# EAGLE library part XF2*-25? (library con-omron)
OMRON FPC Connector Source : http://www.omron.com/ecb/products/pdf/fpc.pdf
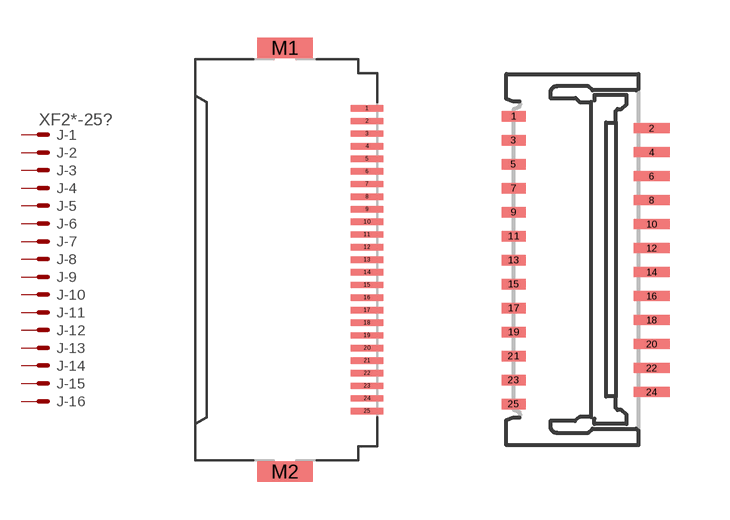
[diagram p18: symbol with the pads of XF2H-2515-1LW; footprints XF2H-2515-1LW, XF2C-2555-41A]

Designator prefix J; gates -1=PV -2=P -3=P -4=P -5=P -6=P -7=P -8=P -9=P -10=P -11=P -12=P -13=P -14=P -15=P -16=P -17=P -18=P -19=P -20=P -21=P -22=P -23=P -24=P -25=P

## XF2H-2515-1LW (OC_FARNELL: unknown; OC_NEWARK: unknown)  [XF2H-2515-1LW]
1  -1:MSV  pas
2  -2:MS  pas
3  -3:MS  pas
4  -4:MS  pas
5  -5:MS  pas
6  -6:MS  pas
7  -7:MS  pas
8  -8:MS  pas
9  -9:MS  pas
10  -10:MS  pas
11  -11:MS  pas
12  -12:MS  pas
13  -13:MS  pas
14  -14:MS  pas
15  -15:MS  pas
16  -16:MS  pas
17  -17:MS  pas
18  -18:MS  pas
19  -19:MS  pas
20  -20:MS  pas
21  -21:MS  pas
22  -22:MS  pas
23  -23:MS  pas
24  -24:MS  pas
25  -25:MS  pas

## XF2C-2555-41A (MPN: XF2C-2555-41A; OC_FARNELL: unknown; OC_NEWARK: 78M3584)  [XF2C-2555-41A]
Pads as for XF2H-2515-1LW

## Footprint XF2H-2515-1LW (pad centres in mm)
Standard Rotary Backlock Type (0.5 mm-pitch) Source : http://www.omron.com/ecb/products/pdf/fpc.pdf
smd 1.3 x 0.25: 1 3.175,6; 2 3.175,5.5; 3 3.175,5; 4 3.175,4.5; 5 3.175,4; 6 3.175,3.5; 7 3.175,3; 8 3.175,2.5; 9 3.175,2; 10 3.175,1.5; 11 3.175,1; 12 3.175,0.5; 13 3.175,0; 14 3.175,-0.5; 15 3.175,-1; 16 3.175,-1.5; 17 3.175,-2; 18 3.175,-2.5; 19 3.175,-3; 20 3.175,-3.5; 21 3.175,-4; 22 3.175,-4.5; 23 3.175,-5; 24 3.175,-5.5; 25 3.175,-6
smd 2.2 x 0.8: M1 -0.075,8.4; M2 -0.075,-8.4

## Footprint XF2C-2555-41A (pad centres in mm)
Low-profile Rotary Backlock Type (0.3 mm-pitch) Source : http://www.omron.com/ecb/products/pdf/fpc.pdf
smd 0.6 x 0.26: 1 -1.8,3.6; 3 -1.8,3; 5 -1.8,2.4; 7 -1.8,1.8; 9 -1.8,1.2; 11 -1.8,0.6; 13 -1.8,0; 15 -1.8,-0.6; 17 -1.8,-1.2; 19 -1.8,-1.8; 21 -1.8,-2.4; 23 -1.8,-3; 25 -1.8,-3.6
smd 0.9 x 0.25: 2 1.65,3.3; 4 1.65,2.7; 6 1.65,2.1; 8 1.65,1.5; 10 1.65,0.9; 12 1.65,0.3; 14 1.65,-0.3; 16 1.65,-0.9; 18 1.65,-1.5; 20 1.65,-2.1; 22 1.65,-2.7; 24 1.65,-3.3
